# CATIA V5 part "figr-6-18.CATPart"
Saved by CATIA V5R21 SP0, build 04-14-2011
Part number: Part1
Bounding box of the stored display mesh (mm): x 0 to 150, y -70 to 70, z -150 to 69.804
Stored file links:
  D:\CATIA V5R21 E-RESOURCES\CATIA-V5R21\catia-v5r21-prt\c06-catia-v5r21-prt\c06-catia-v5r21-figr-6-18.CATPart
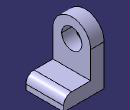
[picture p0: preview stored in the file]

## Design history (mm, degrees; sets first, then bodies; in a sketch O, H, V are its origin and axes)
Body1 (main body)
  Sketch1 on yz-plane, origin (0, 0, 0), H (0, 1, 0), V (0, 0, 1)
    arc A1 centre (0, 0) radius 70 from (70, 0) to (-70, 0) ccw
    point P1 (70, 0)
    point P2 (-70, 0)
    line L1 (-70, 0) -> (-70, -150)
    line L2 (-70, -150) -> (70, -150)
    line L3 (70, -150) -> (70, 0)
    circle A2 centre (0, 0) radius 37.5
    radius A1 = 70
    radius A2 = 37.5
    distance O L2 = 150
    coincidence: P1 H, P2 H
    tangency: L1 A1, L3 A1
    horizontal: L2 H
  Pad1: profile Sketch1, direction (1, 0, 0), length 50
  Sketch2 on face of Pad1, origin (50, 0, 0), H (0, 1, 0), V (0, 0, 1)
    line L1 (-70, -150) -> (70, -150)
    line L2 (70, -150) -> (70, -100)
    line L3 (70, -100) -> (-70, -100)
    line L4 (-70, -100) -> (-70, -150)
    reference projected line E1 (-70, -150) -> (70, -150) from edge [face of Pad1 | face of Pad1]
    reference projected line E2 (-70, 0) -> (-70, -150) from edge [face of Pad1 | face of Pad1]
    reference projected line E3 (70, -150) -> (70, 0) from edge [face of Pad1 | face of Pad1]
    length L2 = 50
    horizontal: L1 H, L3 H
    vertical: L2 V, L4 V
    coincidence: L1 E1, E2 L4, L2 E3
  Pad2: profile Sketch2, direction (1, 0, 0), length 100
  Fillet1: radius 30, on edge [face of Pad2 | face of Pad2]
  Sketch3 on face of Pad1, origin (50, 0, 0), H (0, 1, 0), V (0, 0, 1)
    point P1 (45.5554, 53.148)
    reference projected arc E1 centre (0, 0) radius 70 from (70, 0) to (-70, 0) ccw from edge [face of Pad1 | face of Pad1]
    coincidence: P1 E1
  Sketch4 on face of Pad2, origin (0, 0, -100), H (1, 0, 0), V (0, 1, 0)
    point P1 (110, 20)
